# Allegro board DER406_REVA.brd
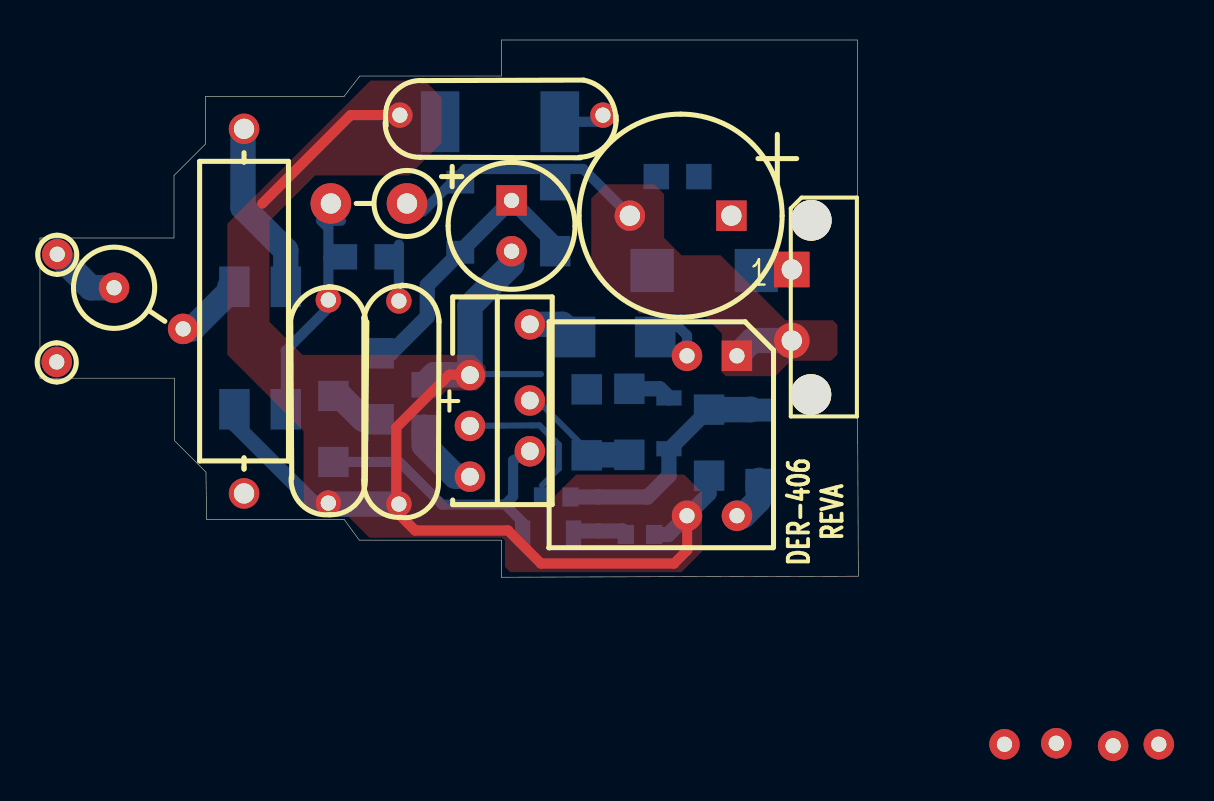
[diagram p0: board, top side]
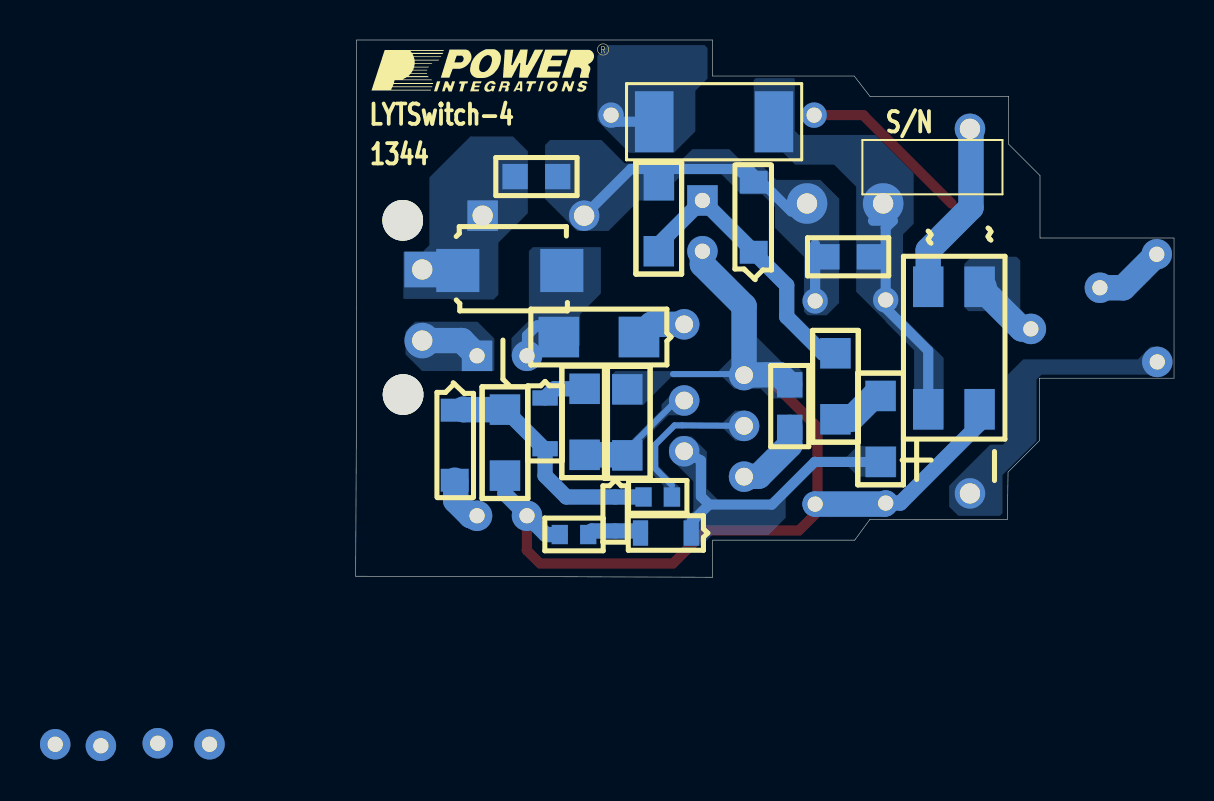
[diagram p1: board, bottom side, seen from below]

Outline 40.94 x 26.87 mm; copper layers: TOP, BOTTOM. Coordinates in mm from the lower left corner of the outline.
Outline path: 0,16.97 6.71,16.97 6.71,20.09 8.28,21.67 8.28,24.05 15.21,24.05 16,25.07 23.09,25.07 23.09,26.87 40.89,26.87 40.89,13.46 40.94,0.05 23.09,0 23.09,1.85 15.98,1.85 15.21,2.9 8.33,2.9 8.31,5.26 6.73,6.83 6.73,9.96 0,9.96 0,16.97

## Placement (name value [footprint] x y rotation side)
BR1  B10S-G  [PISMSOIC4]  9.73 14.53 0 bottom
C1  47 nF  [PINPCAPRAD500X240400040]  28.19 23.14 180 top
C2  47 nF  [PINPCAPRAD500X240400040]  14.4 13.89 270 top
C3  47 nF  [PINPCAPRAD500X240400040]  17.93 13.84 270 top
C4  2.2 uF  [PIPOLCAPCYLD250LS100030]  23.6 18.85 270 top
C5  100 uF  [PISMC1206]  27.36 6.1 90 bottom
C6  4.7 uF  [PISMC1206]  33.48 8.38 270 bottom
C7  220 uF  [PIPOLCAPCYLD400LS200040]  34.59 18.08 180 top
D1  UFM15PL-TP  [PI_SM_SOD-123_12]  21.03 16.26 90 bottom
D2  MURS160T3G  [PISMSMB]  35.84 15.34 180 bottom
D3  STPS2H100AY  [PISMDSMA]  26.77 12.01 0 bottom
D4  BAV21WS-7-F  [PISMSOD323]  31.47 8.97 270 bottom
D5  UFM15PL-TP  [PI_SM_SOD-123_12]  35.99 8.36 270 bottom
D6  BAV16WS-7-F  [PISMSOD323]  24.16 2.21 0 bottom
F1  5 A  [PI_V_AXIAL_160LS150D030]  3.71 14.48 326.8 top
J1  CON2  [PI_CONN_LEE_LEDS]  37.62 15.39 0 top
L  PCB Terminal 30 AWG  [PI_HOLE_30AWG]  0.86 16.15 0 top
L1  4.7 mH  [PI12WVRESD180LS150D040]  18.36 18.69 180 top
N  PCB Terminal 30 AWG  [PI_HOLE_30AWG]  0.84 10.77 0 top
NOREF  -  []  40.94 0.05 90 top
NOREF#2  -  []  -228.6 -131.32 0 top
NOREF#3  -  []  6.71 16.97 0 top
NOREF#4  -  []  -150.78 67.7 0 top
NOREF#5  -  []  16 25.07 0 top
NOREF#6  -  []  0 16.97 0 top
NOREF#7  -  []  23.09 1.85 90 top
NOREF#8  -  []  0 9.96 90 top
NOREF#9  -  []  23.09 26.87 0 top
NOREF#10  -  []  15.21 2.9 90 top
NOREF#11  -  []  40.16 24.28 180 bottom
R1  390  [PI3WRESD230LS775050]  10.21 13.31 90 top
R2  1 k  [PISMR2512]  26.01 22.78 180 bottom
R3  10 k  [PISMR0805]  15.24 16.03 0 bottom
R4  510 k  [PISMR1206]  25.78 19.61 270 bottom
R5  1.80 M  [PISMR1206]  16.94 11.2 270 bottom
R6  1.80 M  [PISMR1206]  14.68 9.07 270 bottom
R7  24.9 k  [PISMR0805]  19.23 9.63 270 bottom
R8  309 k  [PISMR0603]  25.12 4.01 0 bottom
R9  5.1 k  [PISMR1206]  29.49 9.42 270 bottom
R11  510 k  [PISMR0805]  30.84 20.04 0 bottom
R12  10 k  [PISMR0603]  29.31 2.13 0 bottom
T1  EE10  [PI_BOBBIN_EE10_8P]  34.87 11.07 270 top
U1  LYT4322E  [PIICESIP76TH]  21.51 5.03 90 top
VR1  EDZTE6127B  [PISMDSOD52312]  27.97 4.01 270 bottom

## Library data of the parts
BR1 = DIODE BRIDGE_~~+-: room: 1
C1-C3 C5 C6 = CAP NP
C4 = CAP POL: alternate symbols: (pipolcapcyld250ls100030h)
C7 = CAP POL: alternate symbols: (pipolcapclyd395x630ls200030h)
D1 D2 D4-D6 = DIODE
D3 = DIODE SCHOTTKY
F1 = FUSE
J1 = CON2
L N = TERM_1Pin
L1 = INDUCTOR: room: 1
R1 = R: alternate symbols: (pi3wresd230ls775050)
R2 R3 = R: room: 1
R4-R9 R11 R12 = R
T1 = BEE16_8P/GENERIC
U1 = LNK40X_eSIP
VR1 = DIODE_ZENER

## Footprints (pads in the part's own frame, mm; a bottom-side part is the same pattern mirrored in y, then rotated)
PI3WRESD230LS775050
  round 1.524 hole 1.016: 1(-9.119,0) 2(9.119,0)
PI12WVRESD180LS150D040
  round 2.032 hole 1.016: 1(0,0) 2(3.81,0)
PI_BOBBIN_EE10_8P
  rect 1.524x1.524 hole 0.762: 1(0,0)
  round 1.524 hole 0.762: 2(0,-2.499) 3(19.431,21.107) 4(19.507,18.821) 5(19.431,13.386) 6(19.38,15.977) 7(8.001,-2.499) 8(8.001,0)
PI_CONN_LEE_LEDS
  round 2.032 hole 2.032: (0.958,-6.256) (0.975,2.459)
  rect 1.778x1.778 hole 1.016: 1(0,0)
  round 1.778 hole 1.016: 2(0,-3.556)
PI_HOLE_30AWG
  round 1.524 hole 0.762: 1(0,0)
PI_SM_SOD-123_12
  rect 1.143x1.397 smd: 1(0,0) 2(3.505,0)
PI_V_AXIAL_160LS150D030
  round 1.524 hole 0.762: 1(0,0) 2(4.017,0.173)
PIICESIP76TH
  round 1.524 hole 0.889: 1(0,0) 2(1.27,-2.997) 3(2.54,0) 4(3.81,-2.997) 5(5.08,0) 7(7.62,-2.997)
PINPCAPRAD500X240400040
  round 1.27 hole 0.762: 1(0.025,0.025) 2(10.185,0.025)
PIPOLCAPCYLD250LS100030
  rect 1.524x1.524 hole 0.762: 1(0,0)
  round 1.524 hole 0.762: 2(2.54,0)
PIPOLCAPCYLD400LS200040
  rect 1.524x1.524 hole 1.016: 1(0,0)
  round 1.524 hole 1.016: 2(5.08,0)
PISMC1206
  rect 1.524x1.524 smd: 1(0,0) 2(3.302,0)
PISMDSMA
  rect 2.032x2.032 smd: 1(0,0) 2(4.013,0)
PISMDSOD52312
  rect 0.699x0.8 smd: 1(0,0) 2(1.7,0)
PISMR0603
  rect 0.813x0.965 smd: 1(0,0) 2(1.422,0)
PISMR0805
  rect 1.27x1.27 smd: 1(0,0) 2(2.134,0)
PISMR1206
  rect 1.524x1.524 smd: 1(0,0) 2(3.302,0)
PISMR2512
  rect 1.93x3.048 smd: 1(0,0) 2(5.994,0)
PISMSMB
  rect 2.159x2.159 smd: 1(0,0) 2(5.207,0)
PISMSOD323
  rect 0.762x1.27 smd: 1(0,0) 2(2.54,0)
PISMSOIC4
  rect 1.524x2.032 smd: 1(0,0) 2(2.571,0) 3(2.571,6.129) 4(0,6.129)

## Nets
N1678526: BR1.4 C1.2 C2.2 C3.2 C4.2 C5.2 C6.2 R7.1 R12.2 T1.7 U1.5(S)
N2200496: C4.1 D1.1 R4.2 R5.1
N2492766: R7.2 U1.1(R)
N2493445: C3.1 C7.2 D1.2 J1.2 L1.1 R3.2 R4.1 R11.1 T1.1
N2536376: BR1.2 R1.2
N2538393: BR1.3 C2.1 L1.2 R2.2 R3.1
N3672068: C7.1 D2.1 J1.1 R11.2
N3708225: C6.1 D4.2 D5.1 R8.2 VR1.1
N3711440: D2.2 D3.2 T1.2
N3826642: C1.1 R2.1
N3864850: D5.2 T1.8
N3866232: C5.1 R9.2 U1.4(BP)
N3866262: D4.1 R9.1
N3867131: D3.1 U1.7(D)
N3867249: R8.1 U1.3(FB)
N3868462: D6.1 R6.2 U1.2(V)
N3869103: N.1 R1.1
N3869150: F1.1 L.1
N3869154: BR1.1 F1.2
N3875066: D6.2 R12.1 VR1.2
N25419411: R5.2 R6.1

Pads without a net: T1 3 4 5 6

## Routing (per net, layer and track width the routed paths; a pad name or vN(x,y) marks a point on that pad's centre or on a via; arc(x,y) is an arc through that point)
N1678526: length 64.1
  TOP w0.508: T1.7 32.39,3.06 32.39,1.35 31.72,0.69 25.07,0.69 23.42,2.34 18.77,2.34 17.96,3.15 C3.2 17.83,3.78 17.83,7.49 20.47,10.13 U1.5 ; C1.2 15.54,23.11 11.13,18.69
  BOTTOM w0.305: 21.18,10.16 25.07,10.16
  BOTTOM w0.508: 21.08,10.26 21.18,10.16
  BOTTOM w0.762: BR1.4 9.73,7.67 13.69,3.71 C2.2 ; C6.2 33.48,4.18 T1.7 31.44,2.13 R12.2
  BOTTOM w1.27: 33.53,5.03 C6.2 ; R7.1 19.74,10.13 U1.5 21.51,13.56 23.6,15.65 C4.2 ; C3.2 14.48,3.66 C2.2
N2200496: length 14.4
  BOTTOM w0.508: D1.1 21.18,16.41
  BOTTOM w0.762: R5.1 17.55,11.2 19.38,13.03 19.38,14.61 D1.1 21.03,16.28 C4.1 25.78,16.66 R4.2
N2492766: length 3.8
  BOTTOM w1.27: R7.2 19.23,6.6 20.78,5.05 U1.1
N2493445: length 20.7
  BOTTOM w0.508: 25.78,20.42 27.18,20.42 C7.2 ; 25.78,20.42 21.67,20.42 ; 25.78,20.42 R4.1 ; 21.67,20.42 21.77,20.32 D1.2 ; 21.67,20.42 21.29,20.42 19.15,18.29 ; 34.77,11.18 T1.1 ; R3.2 17.88,16.03 17.96,15.95 ; C3.1 17.96,15.95 ; 17.96,15.95 17.96,16.64
  BOTTOM w1.27: T1.1 35.64,11.84 J1.2
N2536376: length 8.8
  BOTTOM w1.27: R1.2 10.16,22.38 10.16,18.49 12.3,16.35 BR1.2
N2538393: length 12.3
  BOTTOM w0.508: 14.43,15.95 C2.1 14.43,13.46 12.3,11.33 BR1.3 ; 14.43,15.95 14.5,16.03 R3.1 ; 14.43,15.95 14.43,17.48 14.07,17.83 15.06,17.83
N3708225: length 12.2
  BOTTOM w0.762: D5.1 36.02,8.41 35.56,8.41 ; C6.1 31.52,6.43 D4.2 31.47,5.08 30.4,4.01 VR1.1 R8.2
  BOTTOM w1.27: C6.1 35.56,8.38 35.56,8.41
N3711440: length 3.2
  BOTTOM w0.508: D3.2 31.87,12.6 32.37,12.09 T1.2 32.54,11.24
N3826642: length 2.3
  BOTTOM w0.508: C1.1 27.84,22.78 R2.1
N3864850: length 2.4
  BOTTOM w1.27: T1.8 35.18,3.07 35.94,3.84 35.94,4.8 D5.2
N3866232: length 6.5
  BOTTOM w0.305: 24.89,8.84 27.36,6.38 C5.1 ; 24.89,8.84 U1.4 24.59,8.86 ; 24.89,8.84 25.04,8.84
  BOTTOM w1.27: C5.1 27.38,6.12 R9.2
N3866262: length 2.2
  BOTTOM w0.762: R9.1 31.01,9.42 D4.1
N3867131: length 2.5
  BOTTOM w1.27: D3.1 26.14,12.65 U1.7
N3867249: length 7.2
  BOTTOM w0.305: 25.12,4.6 25.96,5.44 25.96,6.63 24.99,7.59 24.61,7.59 U1.3
N3868462: length 14.6
  BOTTOM w0.508: U1.2 23.67,5.84 23.67,4.04 23.27,3.63 ; 23.27,3.63 24.16,2.74 D6.1 ; 23.27,3.63 20.12,3.63 17.98,5.77 R6.2
N3869150: length 3.5
  BOTTOM w1.27: L.1 2.54,14.48 F1.1
N3869154: length 3.7
  BOTTOM w1.27: F1.2 7.62,12.42 BR1.1 9.5,14.53
N3875066: length 2.7
  BOTTOM w0.762: R12.1 29.13,2.31 VR1.2 26.8,2.31 D6.2
N25419411: length 2.7
  BOTTOM w1.27: R6.1 15.01,9.07 16.18,7.9 R5.2

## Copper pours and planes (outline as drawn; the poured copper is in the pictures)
N1678526 on TOP: 19.25,24.84 16.54,24.84 9.37,17.68 9.37,11.13 13.2,7.3 13.2,3.72 13.87,3.05 15.42,3.05 16.48,1.98 23.11,1.98 23.27,1.83 23.27,0.51 23.52,0.25 32.11,0.25 33.12,1.27 33.12,4.24 32.23,5.13 26.82,5.13 25.32,3.63 20.42,3.63 19.81,4.24 19.81,8.81 20.35,9.35 21.87,9.35 22.3,9.78 22.3,10.54 21.72,11.13 13.13,11.13 11.48,12.78 11.48,17.81 13.77,20.09 18.47,20.09 20.09,21.72 20.09,24
N1678526 on BOTTOM: 24.94,10.31 24.89,10.26 24.89,10.08 24.97,10.01 25.17,10.01 26.54,8.64 27,8.64 27.03,8.61 28.02,8.61 28.09,8.69 28.09,10.16 27.94,10.31
N1678526 on BOTTOM: 19.02,10.72 19.58,10.72 20.98,12.12 22.78,10.31 22.78,10.21 22,9.42 20.68,9.42 20.19,8.94 18.59,8.94 18.59,10.29
N2493445 on TOP: 31.23,16.98 32.11,16.1 34.06,16.1 37.31,12.85 39.67,12.85 39.9,12.62 39.9,11.15 39.57,10.82 37.57,10.82 36.8,10.06 34.32,10.06 34.11,10.26 34.11,12.19 33.12,13.18 30,13.18 27.58,15.6 27.58,18.95 28.3,19.66 30.73,19.66 31.23,19.16
N2493445 on BOTTOM: 21.54,20.7 22.25,21.41 24.1,21.41 24.82,20.7 27.48,20.7 28.65,21.87 31.24,21.87 31.24,21.84 31.47,21.62 31.47,18.92 29.87,17.32 28.3,17.32 26.77,18.85 25.02,18.85 24.99,18.87 24.99,19.71 25.02,19.74 24.59,20.17 22.66,20.17 21.64,19.15 20.6,19.15 19.96,18.52 19.96,17.48 18.52,16.03 18.52,13.28 18.34,13.11 17.37,13.11 16.76,13.72 16.76,15.37 16.74,15.39 16.74,16.71 16.75,16.73 16.75,18.94 17.69,19.88 19.9,19.88 20.73,20.7
N2493445 on BOTTOM: 37.97,12.78 34.85,12.78 34.01,11.94 34.01,10.36 34.06,10.31 37.62,10.31 38.46,11.15 38.46,12.29
N2538393 on BOTTOM: 21.03,24.87 21.03,21.29 20.98,21.23 19.56,21.23 18.96,20.64 17.01,20.64 15.9,19.53 15.9,14.27 14.43,12.8 14.43,12.78 13,11.35 13,7.44 13.06,7.39 11.61,7.39 11.53,7.47 11.53,10.97 13.56,13 13.56,17.14 13.03,17.68 13.03,20.22 14.94,22.12 18.77,22.12 18.97,22.33 18.97,24.92 19.02,24.97 20.93,24.97
N3672068 on BOTTOM: 37.26,16.61 37.59,16.28 38.56,16.28 38.56,13.92 36.2,13.92 36.17,13.89 34.04,13.89 33.81,14.12 33.81,16.74 32.33,18.21 32.33,21.31 33.07,22.05 35.15,22.05 35.18,22.07 37.26,19.99
N3711440 on BOTTOM: 33.15,11.96 33.15,11.07 32.97,10.9 31.8,10.9 31.67,11.02 31.67,11.25 31.75,11.33 31.5,11.58 29.72,11.58 29.72,13.16 28.68,14.2 28.68,16.48 28.7,16.51 32.08,16.51 32.28,16.31 32.28,12.83
N3826642 on BOTTOM: 23.95,24.33 23.34,24.94 23.34,26.47 23.5,26.62 28.32,26.62 28.85,26.09 28.85,22.83 27.25,21.23 25.02,21.23 23.95,22.3
N3866232 on BOTTOM: 24.23,8.1 24.1,8.23 24.1,8.99 24.36,9.25 25.04,9.25 25.64,8.65 25.64,8.37 27.46,6.55 27.46,6.35 27.05,6.35 25.3,8.1
N3867249 on BOTTOM: 25.55,4.6 26.11,5.16 26.11,5.74 26.04,5.82 25.83,5.82 25.81,5.79 25.81,5.56 24.71,4.47 24.71,3.53 24.74,3.51 25.55,3.51
N3867249 on BOTTOM: 21.56,8.33 21.97,8.33 22.71,7.59 21.95,6.83 21.54,6.83 21.18,7.19 21.18,7.95
N3868462 on BOTTOM: 23.77,1.57 23.65,1.57 23.09,2.13 20.27,2.13 19.43,2.97 19.43,3.99 20.12,3.99 20.32,3.78 22.73,3.78 23.39,4.44 23.39,4.47 23.38,4.48 23.38,6.29 24.13,7.04 24.84,7.04 25.25,6.63 25.25,5.99 24.05,4.8 24.05,3.3 24.54,2.82 24.54,1.55 23.8,1.55
N3868462 on BOTTOM: 13.89,6.55 15.85,6.55 16.59,5.82 15.8,5.03 13.89,5.03
N3869103 on BOTTOM: 7.54,10.9 8.31,10.13 8.31,6.88 8.56,6.63 9.19,6.63 11.25,4.57 11.25,3.53 10.8,3.07 8.71,3.07 8.59,3.2 8.59,5.11 6.88,6.81 6.88,9.88 6.63,10.13 1.27,10.13 1.19,10.06 0.63,10.62 0.63,11.46 0.69,11.51 0.71,11.51 0.74,11.53 1.17,11.53 1.8,10.9
N3869154 on BOTTOM: 7.7,13.31 7.7,15.85 7.87,16.03 10.13,16.03 10.49,15.67 10.49,13.51 10.29,13.31

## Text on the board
Ref Des/Silkscreen Bottom: S/N | 1344 | LYTSwitch-4
Ref Des/Silkscreen Top: DER-406 | REVA
PEN17: PLEASE DELETE THESE PINS | 13   MATERIAL FR4 COPPER 2oz THICKNESS 0.031"
User.5: FIGURE | SIZE | 30.0 | 35.0 | 40.0 | 80.0 | DRILL CHART: TOP to BOTTOM | ALL UNITS ARE IN MILS | PLATED | QTY | 20 | 6 | 8 | 2
